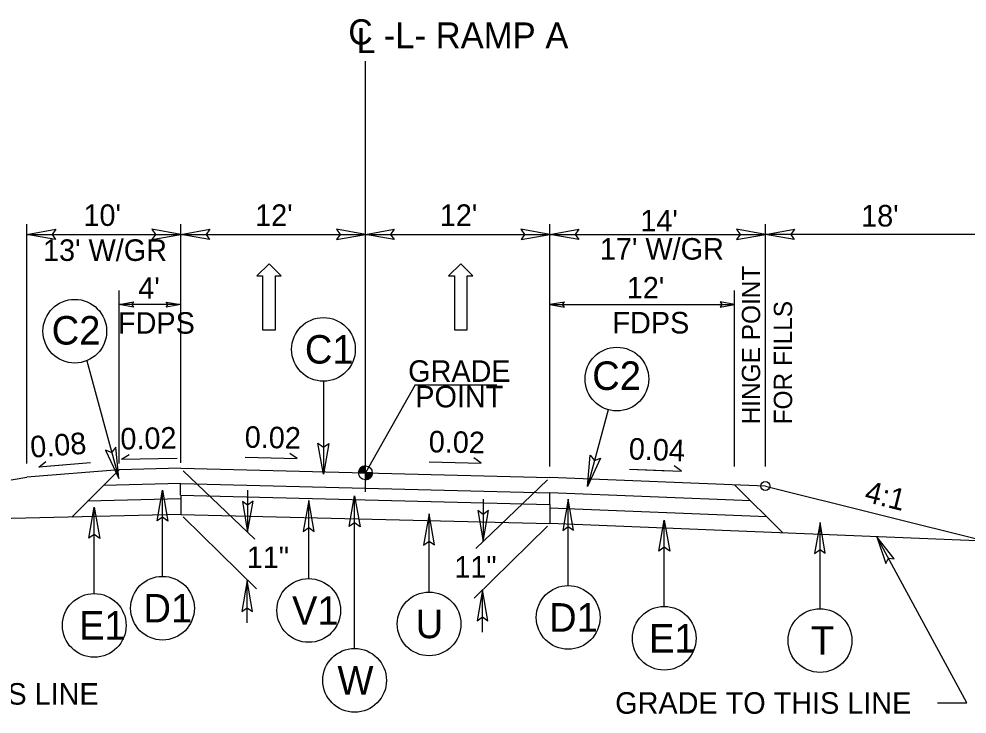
# Model space of a CAD drawing. Extents: x 1640342 to 1730599, y 538663 to 843747.
# Drawn here: x 1729960.9 to 1730022.5, y 539466.4 to 539511.6 of the extents above; entities that cross this region are included whole.
import ezdxf

# ---------------------------------------------------------------- set-up
doc = ezdxf.new("R2010")
doc.units = 0
for name, color, linetype in [('Default', 7, 'Continuous'), ('Prop Dimension Text', 7, 'Continuous'), ('Prop Terminator CELL', 7, 'Continuous'), ('Typical Grade Point Symbol CELL', 7, 'Continuous'), ('Typical Hinge Slope Arterial CELL', 7, 'Continuous'), ('Typical ID Circle CELL', 7, 'Continuous'), ('Typical Pavement Slope CELL', 7, 'Continuous'), ('Typical Pavement Slope Information CELL', 7, 'Continuous'), ('Typical Terminator CELL', 7, 'Continuous'), ('Typical Text Centerline CELL', 7, 'Continuous'), ('Typical Text General CELL', 7, 'Continuous'), ('Typical Text Grade Point CELL', 7, 'Continuous'), ('Typical Text ID Circle CELL', 7, 'Continuous')]:
    doc.layers.add(name, color=color, linetype=linetype)

msp = doc.modelspace()

# ---------------------------------------------------------------- linework, layer by layer
at = {"layer": 'Default'}
for p, q in [((1729961.365, 539482.691), (1729961.365, 539498.258)), ((1729971.365, 539482.74), (1729971.365, 539498.258)), ((1729995.365, 539482.501), (1729995.365, 539498.258)), ((1730009.365, 539482.501), (1730009.365, 539498.258)), ((1729961.365, 539497.589), (1729995.365, 539497.589)), ((1729995.365, 539497.589), (1730009.365, 539497.589)), ((1730024.365, 539497.589), (1730009.365, 539497.589)), ((1729967.365, 539482.691), (1729967.365, 539493.943)), ((1730007.365, 539482.501), (1730007.365, 539493.943)), ((1729971.365, 539493.026), (1729967.365, 539493.026)), ((1729995.365, 539493.026), (1730007.365, 539493.026)), ((1729971.53, 539482.225), (1729976.185, 539477.769)), ((1729995.199, 539481.625), (1729990.544, 539477.169)), ((1729975.717, 539480.967), (1729975.717, 539478.217)), ((1729991.013, 539480.367), (1729991.013, 539477.617)), ((1729971.53, 539479.225), (1729976.292, 539474.532)), ((1729995.199, 539478.625), (1729990.437, 539473.932)), ((1729975.693, 539472.326), (1729975.693, 539475.076)), ((1729990.989, 539471.726), (1729990.989, 539474.476))]:
    msp.add_line(p, q, dxfattribs=at)
for points in [[(1729963.239, 539497.266), (1729961.365, 539497.589), (1729963.249, 539497.922), (1729963.01, 539497.589)], [(1729969.49, 539497.266), (1729971.365, 539497.589), (1729969.48, 539497.922), (1729969.719, 539497.589)], [(1729973.239, 539497.266), (1729971.365, 539497.589), (1729973.249, 539497.922), (1729973.01, 539497.589)], [(1729981.49, 539497.266), (1729983.365, 539497.589), (1729981.48, 539497.922), (1729981.719, 539497.589)], [(1729985.239, 539497.266), (1729983.365, 539497.589), (1729985.249, 539497.922), (1729985.01, 539497.589)], [(1729993.49, 539497.266), (1729995.365, 539497.589), (1729993.48, 539497.922), (1729993.719, 539497.589)], [(1729997.239, 539497.266), (1729995.365, 539497.589), (1729997.249, 539497.922), (1729997.01, 539497.589)], [(1730007.49, 539497.266), (1730009.365, 539497.589), (1730007.48, 539497.922), (1730007.719, 539497.589)], [(1730011.239, 539497.266), (1730009.365, 539497.589), (1730011.249, 539497.922), (1730011.01, 539497.589)], [(1729968.302, 539492.865), (1729967.365, 539493.026), (1729968.307, 539493.193), (1729968.187, 539493.026)], [(1729970.427, 539493.188), (1729971.365, 539493.026), (1729970.422, 539492.86), (1729970.542, 539493.026)], [(1729996.302, 539493.188), (1729995.365, 539493.026), (1729996.307, 539492.86), (1729996.187, 539493.026)], [(1730006.427, 539492.865), (1730007.365, 539493.026), (1730006.422, 539493.193), (1730006.542, 539493.026)]]:
    msp.add_lwpolyline(points, close=True, dxfattribs=at)
at = {"layer": 'Prop Terminator CELL'}
msp.add_lwpolyline([(1730017.732, 539476.498), (1730016.603, 539477.933), (1730017.183, 539476.189), (1730017.355, 539476.544)], close=True, dxfattribs=at)
at = {"layer": 'Typical Grade Point Symbol CELL'}
for p, q in [((1729983.365, 539482.084), (1729983.365, 539482.531)), ((1729982.917, 539482.084), (1729983.365, 539482.084)), ((1729983.366, 539481.636), (1729983.365, 539482.084)), ((1729983.812, 539482.084), (1729983.365, 539482.084)), ((1729983.365, 539482.084), (1729983.366, 539481.636))]:
    msp.add_line(p, q, dxfattribs=at)
for points in [[(1729982.976, 539482.304), (1729982.976, 539482.084)], [(1729982.985, 539482.319), (1729982.985, 539482.084)], [(1729982.994, 539482.333), (1729982.994, 539482.084)], [(1729983.003, 539482.346), (1729983.003, 539482.084)], [(1729983.012, 539482.358), (1729983.012, 539482.084)], [(1729983.021, 539482.369), (1729983.021, 539482.084)], [(1729983.03, 539482.38), (1729983.03, 539482.084)], [(1729983.039, 539482.39), (1729983.039, 539482.084)], [(1729983.047, 539482.399), (1729983.047, 539482.084)], [(1729983.056, 539482.408), (1729983.056, 539482.084)], [(1729983.065, 539482.415), (1729983.065, 539482.084)], [(1729983.074, 539482.423), (1729983.074, 539482.084)], [(1729983.083, 539482.431), (1729983.083, 539482.084)], [(1729983.092, 539482.438), (1729983.092, 539482.084)], [(1729983.101, 539482.444), (1729983.101, 539482.084)], [(1729983.11, 539482.451), (1729983.11, 539482.084)], [(1729983.119, 539482.457), (1729983.119, 539482.084)], [(1729983.128, 539482.463), (1729983.128, 539482.084)], [(1729983.137, 539482.468), (1729983.137, 539482.084)], [(1729983.146, 539482.473), (1729983.146, 539482.084)], [(1729983.155, 539482.478), (1729983.155, 539482.084)], [(1729983.164, 539482.483), (1729983.164, 539482.084)], [(1729983.173, 539482.487), (1729983.173, 539482.084)], [(1729983.182, 539482.491), (1729983.182, 539482.084)], [(1729983.191, 539482.495), (1729983.191, 539482.084)], [(1729983.2, 539482.499), (1729983.2, 539482.084)], [(1729983.208, 539482.503), (1729983.208, 539482.084)], [(1729983.217, 539482.506), (1729983.217, 539482.084)], [(1729983.226, 539482.509), (1729983.226, 539482.084)], [(1729983.235, 539482.512), (1729983.235, 539482.084)], [(1729983.244, 539482.514), (1729983.244, 539482.084)], [(1729983.253, 539482.517), (1729983.253, 539482.084)], [(1729983.262, 539482.519), (1729983.262, 539482.084)], [(1729983.271, 539482.521), (1729983.271, 539482.084)], [(1729983.28, 539482.523), (1729983.28, 539482.084)], [(1729983.289, 539482.525), (1729983.289, 539482.084)], [(1729983.298, 539482.526), (1729983.298, 539482.084)], [(1729983.307, 539482.527), (1729983.307, 539482.084)], [(1729983.316, 539482.528), (1729983.316, 539482.084)], [(1729983.325, 539482.529), (1729983.325, 539482.084)], [(1729983.334, 539482.53), (1729983.334, 539482.084)], [(1729983.343, 539482.53), (1729983.343, 539482.084)], [(1729983.352, 539482.531), (1729983.352, 539482.084)], [(1729983.361, 539482.531), (1729983.361, 539482.531), (1729983.361, 539482.084)], [(1729982.922, 539482.147), (1729982.922, 539482.084)], [(1729982.931, 539482.193), (1729982.931, 539482.084)], [(1729982.94, 539482.224), (1729982.94, 539482.084)], [(1729982.949, 539482.249), (1729982.949, 539482.084)], [(1729982.958, 539482.269), (1729982.958, 539482.084)], [(1729982.967, 539482.288), (1729982.967, 539482.084)], [(1729983.371, 539482.084), (1729983.371, 539481.636), (1729983.371, 539481.636)], [(1729983.38, 539482.084), (1729983.38, 539481.636)], [(1729983.389, 539482.084), (1729983.389, 539481.637)], [(1729983.398, 539482.084), (1729983.398, 539481.637)], [(1729983.407, 539482.084), (1729983.407, 539481.638)], [(1729983.416, 539482.084), (1729983.416, 539481.639)], [(1729983.425, 539482.084), (1729983.425, 539481.64)], [(1729983.434, 539482.084), (1729983.434, 539481.642)], [(1729983.443, 539482.084), (1729983.443, 539481.643)], [(1729983.452, 539482.084), (1729983.452, 539481.645)], [(1729983.461, 539482.084), (1729983.461, 539481.647)], [(1729983.47, 539482.084), (1729983.47, 539481.649)], [(1729983.479, 539482.084), (1729983.479, 539481.651)], [(1729983.488, 539482.084), (1729983.488, 539481.654)], [(1729983.497, 539482.084), (1729983.497, 539481.656)], [(1729983.506, 539482.084), (1729983.506, 539481.659)], [(1729983.515, 539482.084), (1729983.515, 539481.662)], [(1729983.524, 539482.084), (1729983.524, 539481.665)], [(1729983.532, 539482.084), (1729983.532, 539481.669)], [(1729983.541, 539482.084), (1729983.541, 539481.673)], [(1729983.55, 539482.084), (1729983.55, 539481.677)], [(1729983.559, 539482.084), (1729983.559, 539481.681)], [(1729983.568, 539482.084), (1729983.568, 539481.685)], [(1729983.577, 539482.084), (1729983.577, 539481.69)], [(1729983.586, 539482.084), (1729983.586, 539481.695)], [(1729983.595, 539482.084), (1729983.595, 539481.7)], [(1729983.604, 539482.084), (1729983.604, 539481.706)], [(1729983.613, 539482.084), (1729983.613, 539481.712)], [(1729983.622, 539482.084), (1729983.622, 539481.718)], [(1729983.631, 539482.084), (1729983.631, 539481.724)], [(1729983.64, 539482.084), (1729983.64, 539481.731)], [(1729983.649, 539482.084), (1729983.649, 539481.738)], [(1729983.658, 539482.084), (1729983.658, 539481.746)], [(1729983.667, 539482.084), (1729983.667, 539481.754)], [(1729983.676, 539482.084), (1729983.676, 539481.762)], [(1729983.685, 539482.084), (1729983.685, 539481.77)], [(1729983.693, 539482.084), (1729983.693, 539481.78)], [(1729983.702, 539482.084), (1729983.702, 539481.79)], [(1729983.711, 539482.084), (1729983.711, 539481.801)], [(1729983.72, 539482.084), (1729983.72, 539481.812)], [(1729983.729, 539482.084), (1729983.729, 539481.824)], [(1729983.738, 539482.084), (1729983.738, 539481.837)], [(1729983.747, 539482.084), (1729983.747, 539481.851)], [(1729983.756, 539482.084), (1729983.756, 539481.867)], [(1729983.765, 539482.084), (1729983.765, 539481.884)], [(1729983.774, 539482.084), (1729983.774, 539481.903)], [(1729983.783, 539482.084), (1729983.783, 539481.923)], [(1729983.792, 539482.084), (1729983.792, 539481.95)], [(1729983.801, 539482.084), (1729983.801, 539481.982)], [(1729983.81, 539482.084), (1729983.81, 539482.035)]]:
    msp.add_lwpolyline(points, dxfattribs=at)
msp.add_circle((1729983.365, 539482.084), 0.447, dxfattribs=at)
for start, end in [(90.00929, 180.00929), (270.00929, 0.00929)]:
    msp.add_arc((1729983.365, 539482.084), 0.447, start, end, dxfattribs=at)
at = {"layer": 'Typical Hinge Slope Arterial CELL'}
msp.add_line((1730009.365, 539481.224), (1730024.365, 539477.474), dxfattribs=at)
msp.add_circle((1730009.365, 539481.224), 0.297, dxfattribs=at)
at = {"layer": 'Typical ID Circle CELL'}
for p, q in [((1729965.266, 539489.376), (1729967.337, 539481.709)), ((1729980.643, 539488.042), (1729980.643, 539481.992)), ((1729999.149, 539486.189), (1729997.797, 539481.186)), ((1729970.183, 539475.354), (1729970.183, 539480.963)), ((1729982.666, 539470.662), (1729982.667, 539480.594)), ((1729965.746, 539474.234), (1729965.746, 539479.844)), ((1729979.687, 539475.206), (1729979.687, 539480.286)), ((1729996.546, 539474.754), (1729996.546, 539480.363)), ((1729987.51, 539474.329), (1729987.51, 539479.409)), ((1730002.788, 539473.398), (1730002.788, 539479.007)), ((1730012.914, 539473.248), (1730012.914, 539478.858))]:
    msp.add_line(p, q, dxfattribs=at)
for centre in [(1729964.483, 539491.294), (1729980.643, 539490.112), (1729999.713, 539488.182), (1729970.183, 539473.283), (1729979.686, 539473.135), (1729987.509, 539472.258), (1729996.546, 539472.683), (1729965.747, 539472.163), (1730002.789, 539471.327), (1730012.913, 539471.177), (1729982.667, 539468.591)]:
    msp.add_circle(centre, 2.071, dxfattribs=at)
at = {"layer": 'Typical Pavement Slope CELL'}
for p, q in [((1729971.365, 539482.74), (1729971.365, 539497.958)), ((1729977.116, 539495.677), (1729976.316, 539494.889)), ((1729977.891, 539494.889), (1729977.116, 539495.677)), ((1729989.575, 539495.677), (1729988.775, 539494.889)), ((1729989.575, 539495.677), (1729988.775, 539494.889)), ((1729990.35, 539494.889), (1729989.575, 539495.677)), ((1729990.35, 539494.889), (1729989.575, 539495.677)), ((1729976.316, 539494.889), (1729976.691, 539494.889)), ((1729976.691, 539494.889), (1729976.691, 539491.389)), ((1729977.516, 539491.389), (1729977.516, 539494.889)), ((1729977.516, 539494.889), (1729977.891, 539494.889)), ((1729988.775, 539494.889), (1729989.15, 539494.889)), ((1729988.775, 539494.889), (1729989.15, 539494.889)), ((1729989.15, 539494.889), (1729989.15, 539491.389)), ((1729989.15, 539494.889), (1729989.15, 539491.389)), ((1729989.975, 539491.389), (1729989.975, 539494.889)), ((1729989.975, 539494.889), (1729990.35, 539494.889)), ((1729989.975, 539491.389), (1729989.975, 539494.889)), ((1729989.975, 539494.889), (1729990.35, 539494.889)), ((1729976.691, 539491.389), (1729977.516, 539491.389)), ((1729989.15, 539491.389), (1729989.975, 539491.389)), ((1729989.15, 539491.389), (1729989.975, 539491.389)), ((1729975.554, 539483.096), (1729978.935, 539483.012)), ((1729978.935, 539483.012), (1729978.452, 539483.352)), ((1729990.895, 539482.712), (1729990.412, 539483.052)), ((1729962.136, 539482.456), (1729962.6, 539482.822)), ((1729965.507, 539482.726), (1729962.136, 539482.456)), ((1729965.507, 539482.726), (1729962.895, 539482.517)), ((1729971.365, 539482.384), (1729967.365, 539482.284)), ((1729971.365, 539482.384), (1729995.365, 539481.784)), ((1729987.514, 539482.796), (1729990.895, 539482.712)), ((1730000.532, 539482.332), (1730003.151, 539482.223)), ((1730000.532, 539482.332), (1730003.911, 539482.191)), ((1730003.911, 539482.191), (1730003.434, 539482.539)), ((1729942.517, 539478.662), (1729961.365, 539481.804)), ((1729967.365, 539482.284), (1729961.365, 539481.804)), ((1729967.365, 539482.284), (1729964.288, 539479.207)), ((1730009.365, 539481.224), (1729995.365, 539481.784)), ((1729971.365, 539481.384), (1729966.339, 539481.258)), ((1729971.346, 539480.634), (1729971.346, 539481.384)), ((1729971.365, 539481.384), (1729995.365, 539480.784)), ((1730007.365, 539481.304), (1730010.491, 539478.177)), ((1729971.346, 539480.634), (1729995.365, 539480.033)), ((1729971.365, 539480.633), (1729971.365, 539479.384)), ((1730008.406, 539480.262), (1729995.365, 539480.784)), ((1729995.365, 539480.033), (1729995.365, 539480.784)), ((1729971.365, 539480.384), (1729965.313, 539480.232)), ((1729995.365, 539480.033), (1729995.365, 539478.784)), ((1729971.365, 539479.384), (1729942.517, 539478.662)), ((1729971.365, 539479.384), (1729995.365, 539478.784)), ((1730009.448, 539479.22), (1729995.365, 539479.783)), ((1730023.655, 539477.651), (1729995.365, 539478.783))]:
    msp.add_line(p, q, dxfattribs=at)
at = {"layer": 'Typical Pavement Slope Information CELL'}
for q in [(1729968.022, 539483.285), (1729971.137, 539483.047)]:
    msp.add_line((1729967.508, 539482.974), q, dxfattribs=at)
at = {"layer": 'Typical Terminator CELL'}
for p, q in [((1730022.457, 539467.119), (1730016.603, 539477.933)), ((1730020.547, 539467.119), (1730022.457, 539467.119))]:
    msp.add_line(p, q, dxfattribs=at)
for points in [[(1729966.479, 539483.558), (1729967.337, 539481.709), (1729967.155, 539483.752), (1729966.877, 539483.411)], [(1729980.989, 539484), (1729980.643, 539481.992), (1729980.286, 539484.011), (1729980.643, 539483.754)], [(1729998.655, 539483.034), (1729997.797, 539481.186), (1729997.979, 539483.228), (1729998.257, 539482.887)], [(1729969.837, 539478.956), (1729970.183, 539480.963), (1729970.54, 539478.944), (1729970.183, 539479.201)], [(1729982.321, 539478.586), (1729982.667, 539480.594), (1729983.023, 539478.575), (1729982.666, 539478.831)], [(1729965.401, 539477.836), (1729965.746, 539479.844), (1729966.103, 539477.825), (1729965.746, 539478.081)], [(1729975.371, 539480.225), (1729975.717, 539478.217), (1729976.073, 539480.236), (1729975.717, 539479.98)], [(1729980.033, 539478.278), (1729979.687, 539480.286), (1729979.33, 539478.267), (1729979.687, 539478.524)], [(1729996.892, 539478.356), (1729996.546, 539480.363), (1729996.19, 539478.344), (1729996.546, 539478.601)], [(1729987.856, 539477.401), (1729987.51, 539479.409), (1729987.153, 539477.39), (1729987.51, 539477.647)], [(1729990.667, 539479.625), (1729991.013, 539477.617), (1729991.369, 539479.636), (1729991.013, 539479.38)], [(1730002.442, 539476.999), (1730002.788, 539479.007), (1730003.145, 539476.988), (1730002.788, 539477.245)], [(1730013.259, 539476.85), (1730012.914, 539478.858), (1730012.557, 539476.839), (1730012.914, 539477.095)], [(1729976.038, 539473.068), (1729975.693, 539475.076), (1729975.336, 539473.057), (1729975.693, 539473.314)], [(1729991.334, 539472.468), (1729990.989, 539474.476), (1729990.632, 539472.457), (1729990.989, 539472.714)]]:
    msp.add_lwpolyline(points, close=True, dxfattribs=at)
at = {"layer": 'Typical Text Centerline CELL'}
msp.add_line((1729983.365, 539480.856), (1729983.365, 539508.856), dxfattribs=at)
at = {"layer": 'Typical Text Grade Point CELL'}
for q in [(1729983.365, 539482.084), (1729991.908, 539487.807)]:
    msp.add_line((1729986.605, 539487.807), q, dxfattribs=at)

# ---------------------------------------------------------------- texts
at = {"layer": 'Default'}
msp.add_text('11"', height=1.4, dxfattribs=at).set_placement((1729975.659, 539475.893))
msp.add_text('11"', height=1.4, rotation=360, dxfattribs=at).set_placement((1729989.147, 539475.266))
at = {"layer": 'Prop Dimension Text'}
for s, p in [("10'", (1729965.045, 539498.139)), ("18'", (1730015.585, 539498.101)), ("13' W/GR", (1729962.419, 539495.864)), ("12'", (1730000.354, 539493.421)), ('FDPS', (1729999.424, 539491.146))]:
    msp.add_text(s, height=1.4, rotation=360, dxfattribs=at).set_placement(p)
for s, p in [("12'", (1729976.203, 539498.139)), ("12'", (1729988.203, 539498.139)), ("14'", (1730001.235, 539497.784)), ("17' W/GR", (1729998.609, 539495.948)), ("4'", (1729968.609, 539493.405)), ('FDPS', (1729967.293, 539491.13))]:
    msp.add_text(s, height=1.4, dxfattribs=at).set_placement(p)
at = {"layer": 'Typical Hinge Slope Arterial CELL'}
for s, height, p in [('HINGE POINT ', 1.18731, (1730009.021, 539485.233)), ('FOR FILLS', 1.1873, (1730011.099, 539485.233))]:
    msp.add_text(s, height=height, rotation=90, dxfattribs=at).set_placement(p)
at = {"layer": 'Typical Pavement Slope CELL'}
msp.add_text('4:1', height=1.4, rotation=345.96376, dxfattribs=at).set_placement((1730015.739, 539480.228))
at = {"layer": 'Typical Pavement Slope Information CELL'}
for s, rotation, p in [('0.02', 1.14574, (1729967.461, 539483.596)), ('0.02', 358.85426, (1729975.516, 539483.722)), ('0.02', 358.85426, (1729987.476, 539483.422)), ('0.08', 4.28757, (1729961.641, 539483.062)), ('0.04', 357.8957, (1730000.467, 539482.959))]:
    msp.add_text(s, height=1.4, rotation=rotation, dxfattribs=at).set_placement(p)
at = {"layer": 'Typical Text Centerline CELL'}
for s, height, rotation, p in [('C', 1.639, 0.04425, (1729982.26, 539509.933)), ('-L- RAMP A', 1.683, 359.94168, (1729984.559, 539509.695)), ('L', 1.64, 359.99115, (1729982.805, 539509.373))]:
    msp.add_text(s, height=height, rotation=rotation, dxfattribs=at).set_placement(p)
at = {"layer": 'Typical Text General CELL'}
msp.add_text('GRADE TO THIS LINE', height=1.4, rotation=360, dxfattribs=at).set_placement((1729946.791, 539467.01))
msp.add_text('GRADE TO THIS LINE', height=1.4, dxfattribs=at).set_placement((1729999.604, 539466.419))
at = {"layer": 'Typical Text Grade Point CELL'}
for s, p in [('GRADE', (1729986.148, 539488.001)), ('POINT', (1729986.61, 539486.342))]:
    msp.add_text(s, height=1.4, rotation=359.99977, dxfattribs=at).set_placement(p)
at = {"layer": 'Typical Text ID Circle CELL'}
for s, height, p in [('C2', 1.8535, (1729962.98, 539490.425)), ('C1', 1.8535, (1729979.435, 539489.186)), ('C2', 1.8535, (1729998.109, 539487.475)), ('D1', 1.8535, (1729968.945, 539472.356)), ('V1', 1.8535, (1729978.599, 539472.208)), ('E1', 1.8535, (1729964.76, 539471.237)), ('U', 1.854, (1729986.635, 539471.331)), ('D1', 1.8535, (1729995.307, 539471.756)), ('E1', 1.8535, (1730001.802, 539470.4)), ('T', 1.854, (1730012.324, 539470.251)), ('W', 1.854, (1729981.554, 539467.665))]:
    msp.add_text(s, height=height, dxfattribs=at).set_placement(p)

doc.saveas('drawing.dxf')
